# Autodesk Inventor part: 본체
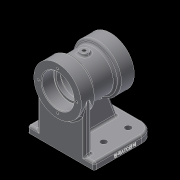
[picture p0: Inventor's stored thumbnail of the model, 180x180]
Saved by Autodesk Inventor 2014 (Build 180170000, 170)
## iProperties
Created: 2020-06
Part Number: 본체
Material: Generic
Document SubType Name: Modeling
Designer: kh
Density: 1 g/cm^3
Appearance: Default
Author: kh
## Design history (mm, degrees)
sketch "Sketch1"
  geometry: L1 (0, 49)-(90, 49); L2 (90, 49)-(90, -49); L3 (90, -49)-(0, -49); L4 (0, -49)-(0, 49); 2 further points
  constraints: 8 end point, 2 coincident, 2 parallel, 1 horizontal, 1 midpoint, 1 perpendicular
  dimensions: "d0" = 90 distance of L1.start L1.end; "d1" = 98 distance of L1.end L2.end
extrude "Extrusion1" new body sketch "Sketch1" distance "d2" = 10; taper "d3" = 0 deg
sketch "Sketch2"
  geometry: L1 (-73, 80)-(5, 80); L2 (5, 80)-(5, 115); L3 (5, 115)-(-17, 115); L4 (-17, 115)-(-17, 109); L5 (-17, 109)-(-51, 109); L6 (-51, 109)-(-51, 115); L7 (-51, 115)-(-73, 115); L8 (-73, 115)-(-73, 80); 1 further point
  constraints: 16 end point, 4 parallel, 2 collinear, 2 vertical, 1 horizontal, 1 perpendicular
  dimensions: "d4" = 70 diameter of L7 L1; "d5" = 58 diameter of L5 L1; "d6" = 78 distance between parallel lines of L2 L8; "d7" = 22 distance of L2.end L3.end; "d9" = 80 vertical distance of point (0, 0) L1.end; "d11" = 5 distance from line of L2 point (0, 0)
revolve "Revolution1" sketch "Sketch2" stored, may be unused: angle "d10" = 90 deg
sketch "Sketch3"
  geometry: L1 (98, 0)-(0, 0) reference; L2 (14, 80)-(84, 80); L3 (84, 80)-(84, 0); L4 (84, 0)-(14, 0); L5 (14, 0)-(14, 80); C1 r 35 at (49, 80) reference; 3 further points
  constraints: 8 end point, 3 midpoint, 2 parallel, 1 coincident, 1 horizontal, 1 perpendicular
  dimensions: "d12" = 70 distance of L2.start L2.end
extrude "Extrusion2" join sketch "Sketch3" distance "d13" = 10; taper "d14" = 0 deg
sketch "Sketch4"
  geometry: L1 (-65.261, 45)-(-78, 10); L2 (0, 10)-(-90, 10) reference; L3 (-73, 45)-(-51, 45) reference; 1 further point
  constraints: 2 end point, 2 point on line
  dimensions: "d15" = 70 deg angle of L2 L1; "d16" = 12 distance of L1.end L2.end
feature "Rib1" sketch "Sketch4" dims "d17" = 1, "d18" = 10, "d19" = 0, "d20" = 0, "d21" = 1, "d22" = 1
workplane "Work Plane2"
  workplane "Work Plane1"
sketch "Sketch6"
  geometry: L1 (-17, -5)-(-17, 5) reference; L2 (-17, -5)-(17, -5) reference; L3 (17, -5)-(17, 5) reference; L4 (17, 5)-(-17, 5) reference; C1 r 6 at (0, 0); 2 further points
  constraints: 1 centre point, 1 horizontal alignment, 1 midpoint, 1 vertical alignment
  dimensions: "d31" = 12 diameter of C1
extrude "Extrusion3" join sketch "Sketch6" stored distance "d32" = 10; taper "d33" = 0 deg
sketch "Sketch5"
  geometry: L1 (5, 45)-(5, 115) reference; L2 (5, 80)-(-73, 80); L3 (-73, 45)-(-73, 115) reference; L4 (5, 103.5)-(-13, 103.5); L5 (-13, 103.5)-(-13, 100); L6 (-13, 100)-(-19, 100); L7 (-19, 100)-(-19, 103); L8 (-19, 103)-(-49, 103); L9 (-49, 103)-(-49, 100); L10 (-49, 100)-(-55, 100); L11 (-55, 100)-(-55, 103.5); L12 (-55, 103.5)-(-73, 103.5); L13 (5, 103.5)-(5, 80); L14 (-73, 103.5)-(-73, 80); 1 further point
  constraints: 24 end point, 6 collinear, 6 parallel, 4 perpendicular, 2 midpoint, 2 point on line
  dimensions: "d24" = 18 distance of L4.start L4.end; "d25" = 30 distance of L7.end L8.end; "d26" = 46 diameter of L8 L2; "d27" = 40 diameter of L6 L2; "d28" = 47 diameter of L4 L2
revolve "Revolution2" sketch "Sketch5" stored, may be unused: angle "d29" = 90 deg
hole "Hole1" diameter "d36" = 5.188; stored, may be unused: countersink angle "d40" = 90 deg, drill point angle "d42" = 118 deg; dims "d34" = 10, "d35" = 10, "d37" = 6, "d38" = 4, "d39" = 2, "d41" = 8
sketch "Sketch7"
  geometry: C1 r 23.5 at (0, 0) reference; 2 further points
  constraints: 1 vertical alignment
  dimensions: "d43" = 28.5 distance of point (0, 28.5) C1.centre
hole "Hole2" sketch "Sketch7" at (0, 28.5) diameter "d44" = 3.242; stored, may be unused: countersink angle "d48" = 90 deg, drill point angle "d50" = 118 deg; dims "d45" = 10, "d46" = 4, "d47" = 2, "d49" = 12
pattern_circular "Circular Pattern1" dims angle "d52" = 360 deg
workplane "Work Plane3"
mirror "Mirror1"
fillet "Fillet1" dims "d54" = 3
fillet "Fillet2" dims "d55" = 0.3
chamfer "Chamfer1" distance "d56" = 1; stored, may be unused: second distance "d57" = 2, angle "d58" = 45 deg
fillet "Fillet3" dims "d59" = 3
fillet "Fillet4" dims "d60" = 3
fillet "Fillet5" dims "d61" = 20
sketch "Sketch8"
  geometry: A1 r 20 centre (-70, -29) between (-90, -29) and (-70, -49) reference; A2 r 20 centre (-70, 29) between (-70, 49) and (-90, 29) reference; 1 further point
hole "Hole3" sketch "Sketch8" at (-70, -29), (-70, 29) diameter "d62" = 9; stored, may be unused: countersink angle "d66" = 90 deg, drill point angle "d68" = 118 deg; dims "d63" = 10, "d64" = 4, "d65" = 2, "d67" = 12
pattern_linear "Rectangular Pattern1" dims "d71" = 36
fillet "Fillet6" dims "d72" = 3
fillet "Fillet7" dims "d73" = 3
sketch "Sketch9"
  geometry: L1 (67, 0)-(0, 0) reference; L2 (-3, 7)-(-3, 0) reference; 1 further point
  constraints: 1 other
  dimensions: "d74" = 4 distance from line of L1 point (42, 4); "d75" = 45 distance from line of point (42, 4) L2
emboss "Emboss1" sketch "Sketch9" dims "d0" = 90, "d1" = 98, "d76" = 0.5, "d77" = 0
body "Solid1"
node "Projected Loop1"
other parameters: "d30" = 3
